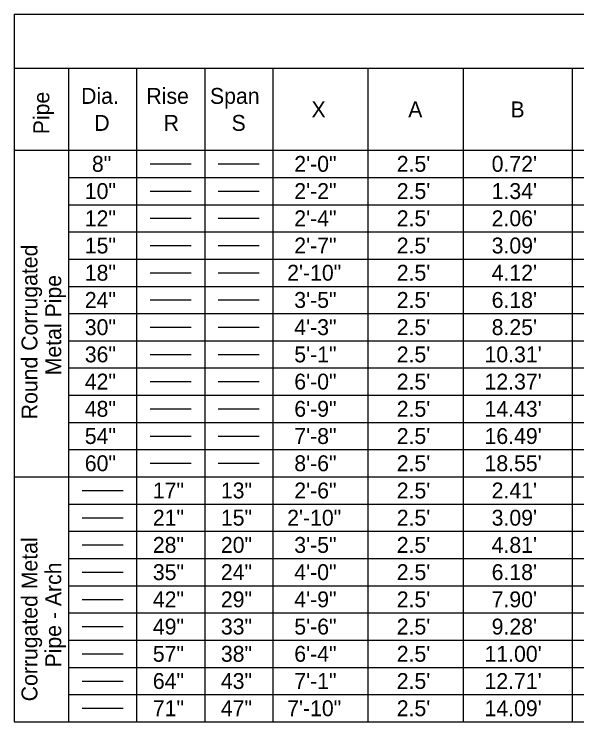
# Model space of a CAD drawing. Extents: x -1.3 to 14.4, y 0 to 6.5.
# Drawn here: x 2 to 4.481, y 3.39 to 6.51 of the extents above; entities that cross this region are included whole.
import ezdxf

# ---------------------------------------------------------------- set-up
doc = ezdxf.new("R2010")
doc.units = 0
doc.layers.add('TextNotes', color=7, linetype='Continuous')
doc.layers.add('TextTables', color=7, linetype='Continuous')

msp = doc.modelspace()

# ---------------------------------------------------------------- linework, layer by layer
at = {"layer": 'TextTables'}
for p, q in [((2, 6.51), (13.4, 6.51)), ((2.6, 5.85), (2.78, 5.85)), ((2.9, 5.85), (3.08, 5.85)), ((2.6, 5.73), (2.78, 5.73)), ((2.9, 5.73), (3.08, 5.73)), ((2.6, 5.61), (2.78, 5.61)), ((2.9, 5.61), (3.08, 5.61)), ((2.6, 5.49), (2.78, 5.49)), ((2.9, 5.49), (3.08, 5.49)), ((2.6, 5.37), (2.78, 5.37)), ((2.9, 5.37), (3.08, 5.37)), ((2.6, 5.25), (2.78, 5.25)), ((2.9, 5.25), (3.08, 5.25)), ((2.6, 5.13), (2.78, 5.13)), ((2.9, 5.13), (3.08, 5.13)), ((2.6, 5.01), (2.78, 5.01)), ((2.9, 5.01), (3.08, 5.01)), ((2.6, 4.89), (2.78, 4.89)), ((2.9, 4.89), (3.08, 4.89)), ((2.6, 4.77), (2.78, 4.77)), ((2.9, 4.77), (3.08, 4.77)), ((2.6, 4.65), (2.78, 4.65)), ((2.9, 4.65), (3.08, 4.65)), ((2.6, 4.53), (2.78, 4.53)), ((2.9, 4.53), (3.08, 4.53)), ((2.3, 4.41), (2.48, 4.41)), ((2.3, 4.29), (2.48, 4.29)), ((2.3, 4.17), (2.48, 4.17)), ((2.3, 4.05), (2.48, 4.05)), ((2.3, 3.93), (2.48, 3.93)), ((2.3, 3.81), (2.48, 3.81)), ((2.3, 3.69), (2.48, 3.69)), ((2.3, 3.57), (2.48, 3.57)), ((2.3, 3.45), (2.48, 3.45))]:
    msp.add_line(p, q, dxfattribs=at)
for points in [[(2, 6.51), (2, 6.27), (2, 5.91), (2, 4.47), (2, 3.39)], [(13.4, 6.27), (11.72, 6.27), (10.04, 6.27), (8.36, 6.27), (8, 6.27), (6.32, 6.27), (5.96, 6.27), (5.6, 6.27), (5.24, 6.27), (4.88, 6.27), (4.46, 6.27), (3.98, 6.27), (3.56, 6.27), (3.14, 6.27), (2.84, 6.27), (2.54, 6.27), (2.24, 6.27), (2, 6.27)], [(2.24, 6.27), (2.24, 5.91), (2.24, 5.79), (2.24, 5.67), (2.24, 5.55), (2.24, 5.43), (2.24, 5.31), (2.24, 5.19), (2.24, 5.07), (2.24, 4.95), (2.24, 4.83), (2.24, 4.71), (2.24, 4.59), (2.24, 4.47), (2.24, 4.35), (2.24, 4.23), (2.24, 4.11), (2.24, 3.99), (2.24, 3.87), (2.24, 3.75), (2.24, 3.63), (2.24, 3.51), (2.24, 3.39)], [(2.54, 6.27), (2.54, 5.91), (2.54, 5.79), (2.54, 5.67), (2.54, 5.55), (2.54, 5.43), (2.54, 5.31), (2.54, 5.19), (2.54, 5.07), (2.54, 4.95), (2.54, 4.83), (2.54, 4.71), (2.54, 4.59), (2.54, 4.47), (2.54, 4.35), (2.54, 4.23), (2.54, 4.11), (2.54, 3.99), (2.54, 3.87), (2.54, 3.75), (2.54, 3.63), (2.54, 3.51), (2.54, 3.39)], [(2.84, 6.27), (2.84, 5.91), (2.84, 5.79), (2.84, 5.67), (2.84, 5.55), (2.84, 5.43), (2.84, 5.31), (2.84, 5.19), (2.84, 5.07), (2.84, 4.95), (2.84, 4.83), (2.84, 4.71), (2.84, 4.59), (2.84, 4.47), (2.84, 4.35), (2.84, 4.23), (2.84, 4.11), (2.84, 3.99), (2.84, 3.87), (2.84, 3.75), (2.84, 3.63), (2.84, 3.51), (2.84, 3.39)], [(3.14, 6.27), (3.14, 5.91), (3.14, 5.79), (3.14, 5.67), (3.14, 5.55), (3.14, 5.43), (3.14, 5.31), (3.14, 5.19), (3.14, 5.07), (3.14, 4.95), (3.14, 4.83), (3.14, 4.71), (3.14, 4.59), (3.14, 4.47), (3.14, 4.35), (3.14, 4.23), (3.14, 4.11), (3.14, 3.99), (3.14, 3.87), (3.14, 3.75), (3.14, 3.63), (3.14, 3.51), (3.14, 3.39)], [(3.56, 6.27), (3.56, 5.91), (3.56, 5.79), (3.56, 5.67), (3.56, 5.55), (3.56, 5.43), (3.56, 5.31), (3.56, 5.19), (3.56, 5.07), (3.56, 4.95), (3.56, 4.83), (3.56, 4.71), (3.56, 4.59), (3.56, 4.47), (3.56, 4.35), (3.56, 4.23), (3.56, 4.11), (3.56, 3.99), (3.56, 3.87), (3.56, 3.75), (3.56, 3.63), (3.56, 3.51), (3.56, 3.39)], [(3.98, 6.27), (3.98, 5.91), (3.98, 5.79), (3.98, 5.67), (3.98, 5.55), (3.98, 5.43), (3.98, 5.31), (3.98, 5.19), (3.98, 5.07), (3.98, 4.95), (3.98, 4.83), (3.98, 4.71), (3.98, 4.59), (3.98, 4.47), (3.98, 4.35), (3.98, 4.23), (3.98, 4.11), (3.98, 3.99), (3.98, 3.87), (3.98, 3.75), (3.98, 3.63), (3.98, 3.51), (3.98, 3.39)], [(4.46, 6.27), (4.46, 5.91), (4.46, 5.79), (4.46, 5.67), (4.46, 5.55), (4.46, 5.43), (4.46, 5.31), (4.46, 5.19), (4.46, 5.07), (4.46, 4.95), (4.46, 4.83), (4.46, 4.71), (4.46, 4.59), (4.46, 4.47), (4.46, 4.35), (4.46, 4.23), (4.46, 4.11), (4.46, 3.99), (4.46, 3.87), (4.46, 3.75), (4.46, 3.63), (4.46, 3.51), (4.46, 3.39)], [(2, 5.91), (2.24, 5.91), (2.54, 5.91), (2.84, 5.91), (3.14, 5.91), (3.56, 5.91), (3.98, 5.91), (4.46, 5.91), (4.88, 5.91)], [(2.24, 5.79), (2.54, 5.79), (2.84, 5.79), (3.14, 5.79), (3.56, 5.79), (3.98, 5.79), (4.46, 5.79), (4.88, 5.79)], [(2.24, 5.67), (2.54, 5.67), (2.84, 5.67), (3.14, 5.67), (3.56, 5.67), (3.98, 5.67), (4.46, 5.67), (4.88, 5.67)], [(2.24, 5.55), (2.54, 5.55), (2.84, 5.55), (3.14, 5.55), (3.56, 5.55), (3.98, 5.55), (4.46, 5.55), (4.88, 5.55)], [(2.24, 5.43), (2.54, 5.43), (2.84, 5.43), (3.14, 5.43), (3.56, 5.43), (3.98, 5.43), (4.46, 5.43), (4.88, 5.43)], [(2.24, 5.31), (2.54, 5.31), (2.84, 5.31), (3.14, 5.31), (3.56, 5.31), (3.98, 5.31), (4.46, 5.31), (4.88, 5.31)], [(2.24, 5.19), (2.54, 5.19), (2.84, 5.19), (3.14, 5.19), (3.56, 5.19), (3.98, 5.19), (4.46, 5.19), (4.88, 5.19)], [(2.24, 5.07), (2.54, 5.07), (2.84, 5.07), (3.14, 5.07), (3.56, 5.07), (3.98, 5.07), (4.46, 5.07), (4.88, 5.07)], [(2.24, 4.95), (2.54, 4.95), (2.84, 4.95), (3.14, 4.95), (3.56, 4.95), (3.98, 4.95), (4.46, 4.95), (4.88, 4.95)], [(2.24, 4.83), (2.54, 4.83), (2.84, 4.83), (3.14, 4.83), (3.56, 4.83), (3.98, 4.83), (4.46, 4.83), (4.88, 4.83)], [(2.24, 4.71), (2.54, 4.71), (2.84, 4.71), (3.14, 4.71), (3.56, 4.71), (3.98, 4.71), (4.46, 4.71), (4.88, 4.71)], [(2.24, 4.59), (2.54, 4.59), (2.84, 4.59), (3.14, 4.59), (3.56, 4.59), (3.98, 4.59), (4.46, 4.59), (4.88, 4.59)], [(2, 4.47), (2.24, 4.47), (2.54, 4.47), (2.84, 4.47), (3.14, 4.47), (3.56, 4.47), (3.98, 4.47), (4.46, 4.47), (4.88, 4.47)], [(2.24, 4.47), (2.54, 4.47), (2.84, 4.47), (3.14, 4.47), (3.56, 4.47), (3.98, 4.47), (4.46, 4.47), (4.88, 4.47)], [(2.24, 4.35), (2.54, 4.35), (2.84, 4.35), (3.14, 4.35), (3.56, 4.35), (3.98, 4.35), (4.46, 4.35), (4.88, 4.35)], [(2.24, 4.23), (2.54, 4.23), (2.84, 4.23), (3.14, 4.23), (3.56, 4.23), (3.98, 4.23), (4.46, 4.23), (4.88, 4.23)], [(2.24, 4.11), (2.54, 4.11), (2.84, 4.11), (3.14, 4.11), (3.56, 4.11), (3.98, 4.11), (4.46, 4.11), (4.88, 4.11)], [(2.24, 3.99), (2.54, 3.99), (2.84, 3.99), (3.14, 3.99), (3.56, 3.99), (3.98, 3.99), (4.46, 3.99), (4.88, 3.99)], [(2.24, 3.87), (2.54, 3.87), (2.84, 3.87), (3.14, 3.87), (3.56, 3.87), (3.98, 3.87), (4.46, 3.87), (4.88, 3.87)], [(2.24, 3.75), (2.54, 3.75), (2.84, 3.75), (3.14, 3.75), (3.56, 3.75), (3.98, 3.75), (4.46, 3.75), (4.88, 3.75)], [(2.24, 3.63), (2.54, 3.63), (2.84, 3.63), (3.14, 3.63), (3.56, 3.63), (3.98, 3.63), (4.46, 3.63), (4.88, 3.63)], [(2.24, 3.51), (2.54, 3.51), (2.84, 3.51), (3.14, 3.51), (3.56, 3.51), (3.98, 3.51), (4.46, 3.51), (4.88, 3.51)], [(2, 3.39), (2.24, 3.39), (2.54, 3.39), (2.84, 3.39), (3.14, 3.39), (3.56, 3.39), (3.98, 3.39), (4.46, 3.39), (4.88, 3.39)]]:
    msp.add_lwpolyline(points, dxfattribs=at)

# ---------------------------------------------------------------- texts
at = {"layer": 'TextNotes'}
for s, p in [('Dia.', (2.2952, 6.1145)), ('Rise', (2.5831, 6.1145)), ('Span', (2.8634, 6.1145)), ('X', (3.3112, 6.055)), ('A', (3.7375, 6.055)), ('B', (4.1883, 6.055)), ('D', (2.3534, 5.9955)), ('R', (2.6592, 5.9955)), ('S', (2.9586, 5.9955))]:
    msp.add_text(s, height=0.07, dxfattribs=at).set_placement(p)
for s, rotation, p in [('Pipe', 90, (2.155, 5.9806)), ('8"', 0, (2.3429, 5.815)), ('2\'-0"', 0, (3.2351, 5.815)), ("2.5'", 0, (3.6869, 5.815)), ("0.72'", 0, (4.1054, 5.815)), ('10"', 0, (2.3115, 5.695)), ('2\'-2"', 0, (3.2351, 5.695)), ("2.5'", 0, (3.6869, 5.695)), ("1.34'", 0, (4.1054, 5.695)), ('12"', 0, (2.3115, 5.575)), ('2\'-4"', 0, (3.2351, 5.575)), ("2.5'", 0, (3.6869, 5.575)), ("2.06'", 0, (4.1054, 5.575)), ('15"', 0, (2.3115, 5.455)), ('2\'-7"', 0, (3.2351, 5.455)), ("2.5'", 0, (3.6869, 5.455)), ("3.09'", 0, (4.1054, 5.455)), ('Round Corrugated', 90, (2.1025, 4.7239)), ('18"', 0, (2.3115, 5.335)), ('2\'-10"', 0, (3.2037, 5.335)), ("2.5'", 0, (3.6869, 5.335)), ("4.12'", 0, (4.1054, 5.335)), ('Metal Pipe', 90, (2.2075, 4.9179)), ('24"', 0, (2.3115, 5.215)), ('3\'-5"', 0, (3.2351, 5.215)), ("2.5'", 0, (3.6869, 5.215)), ("6.18'", 0, (4.1054, 5.215)), ('30"', 0, (2.3115, 5.095)), ('4\'-3"', 0, (3.2351, 5.095)), ("2.5'", 0, (3.6869, 5.095)), ("8.25'", 0, (4.1054, 5.095)), ('36"', 0, (2.3115, 4.975)), ('5\'-1"', 0, (3.2351, 4.975)), ("2.5'", 0, (3.6869, 4.975)), ("10.31'", 0, (4.074, 4.975)), ('42"', 0, (2.3115, 4.855)), ('6\'-0"', 0, (3.2351, 4.855)), ("2.5'", 0, (3.6869, 4.855)), ("12.37'", 0, (4.074, 4.855)), ('48"', 0, (2.3115, 4.735)), ('6\'-9"', 0, (3.2351, 4.735)), ("2.5'", 0, (3.6869, 4.735)), ("14.43'", 0, (4.074, 4.735)), ('54"', 0, (2.3115, 4.615)), ('7\'-8"', 0, (3.2351, 4.615)), ("2.5'", 0, (3.6869, 4.615)), ("16.49'", 0, (4.074, 4.615)), ('60"', 0, (2.3115, 4.495)), ('8\'-6"', 0, (3.2351, 4.495)), ("2.5'", 0, (3.6869, 4.495)), ("18.55'", 0, (4.074, 4.495)), ('17"', 0, (2.6115, 4.375)), ('13"', 0, (2.9115, 4.375)), ('2\'-6"', 0, (3.2351, 4.375)), ("2.5'", 0, (3.6869, 4.375)), ("2.41'", 0, (4.1054, 4.375)), ('21"', 0, (2.6115, 4.255)), ('15"', 0, (2.9115, 4.255)), ('2\'-10"', 0, (3.2037, 4.255)), ("2.5'", 0, (3.6869, 4.255)), ("3.09'", 0, (4.1054, 4.255)), ('Corrugated Metal ', 90, (2.1025, 3.4804)), ('28"', 0, (2.6115, 4.135)), ('20"', 0, (2.9115, 4.135)), ('3\'-5"', 0, (3.2351, 4.135)), ("2.5'", 0, (3.6869, 4.135)), ("4.81'", 0, (4.1054, 4.135)), ('Pipe - Arch', 90, (2.2075, 3.6296)), ('35"', 0, (2.6115, 4.015)), ('24"', 0, (2.9115, 4.015)), ('4\'-0"', 0, (3.2351, 4.015)), ("2.5'", 0, (3.6869, 4.015)), ("6.18'", 0, (4.1054, 4.015)), ('42"', 0, (2.6115, 3.895)), ('29"', 0, (2.9115, 3.895)), ('4\'-9"', 0, (3.2351, 3.895)), ("2.5'", 0, (3.6869, 3.895)), ("7.90'", 0, (4.1054, 3.895)), ('49"', 0, (2.6115, 3.775)), ('33"', 0, (2.9115, 3.775)), ('5\'-6"', 0, (3.2351, 3.775)), ("2.5'", 0, (3.6869, 3.775)), ("9.28'", 0, (4.1054, 3.775)), ('57"', 0, (2.6115, 3.655)), ('38"', 0, (2.9115, 3.655)), ('6\'-4"', 0, (3.2351, 3.655)), ("2.5'", 0, (3.6869, 3.655)), ("11.00'", 0, (4.074, 3.655)), ('64"', 0, (2.6115, 3.535)), ('43"', 0, (2.9115, 3.535)), ('7\'-1"', 0, (3.2351, 3.535)), ("2.5'", 0, (3.6869, 3.535)), ("12.71'", 0, (4.074, 3.535)), ('71"', 0, (2.6115, 3.415)), ('47"', 0, (2.9115, 3.415)), ('7\'-10"', 0, (3.2037, 3.415)), ("2.5'", 0, (3.6869, 3.415)), ("14.09'", 0, (4.074, 3.415))]:
    msp.add_text(s, height=0.07, rotation=rotation, dxfattribs=at).set_placement(p)

doc.saveas('drawing.dxf')
